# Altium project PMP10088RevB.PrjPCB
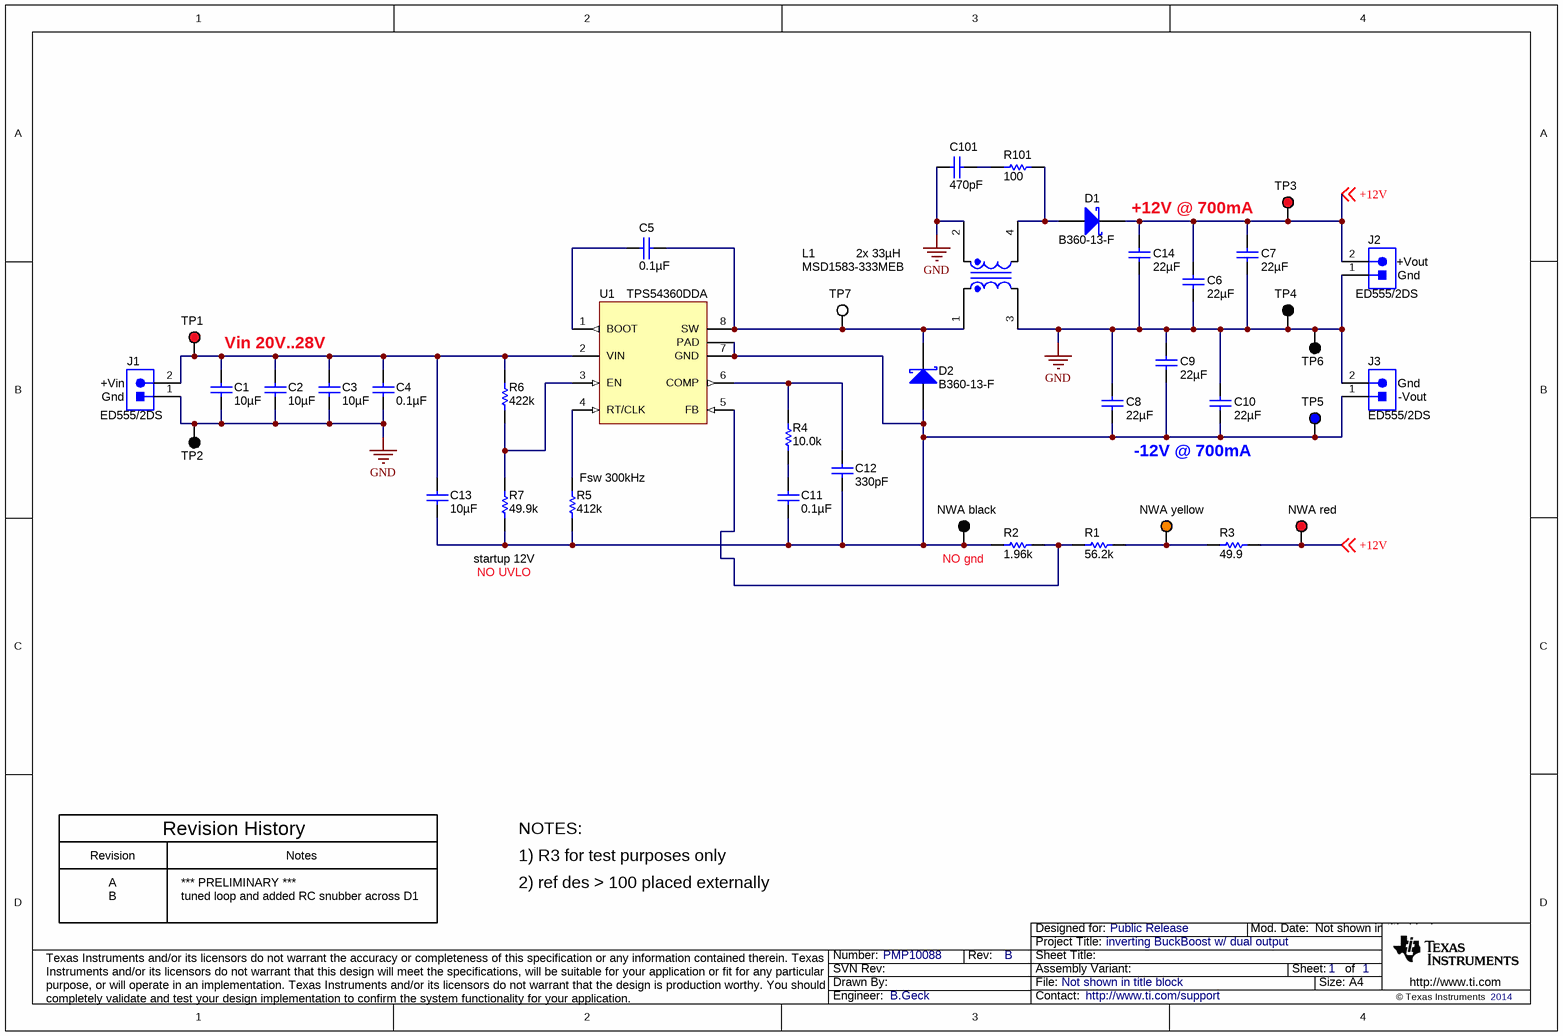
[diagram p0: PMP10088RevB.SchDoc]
TechSupport: http://www.ti.com/support; SCH_Rev: B; PRJ_Title: inverting BuckBoost w/ dual output; PRJ_Number: PMP10088; PRJ_Engineer: B.Geck; PRJ_Customer: Public Release; PCB_Rev: A; PCB_Layout: B.Geck; CopyrightYear: 2014
1 sheet, 40 parts. Net scope: global (net labels, ports and power ports of the same name join across sheets).
Board file: PMP10088RevA.PcbDoc

## Sheet PMP10088RevB.SchDoc
size A4; Date: Not shown in title block; ApprovedBy: Not shown in title block; CheckedBy: Not shown in title block; Author: Not shown in title block; CompanyName: Not shown in title block; Engineer: Not shown in title block; Organization: Not shown in title block; Address1: Not shown in title block; Address2: Not shown in title block; Address3: Not shown in title block; Address4: Not shown in title block; DocumentNumber: 1; Revision: Use project parameter SCH_Rev; SheetNumber: 1; SheetTotal: 1; PageSetup: Record=PageOptions¦CenterHorizontal=True¦CenterVertical=True¦PrintScale=0.70¦XCorrection=1.00¦YCorrection=1.00¦PrintKind=0¦BorderSize=5000000¦LeftOffset=0¦BottomOffset=0¦Orientation=2¦PaperLength=1000¦PaperWidth=1000¦Scale=100¦PaperSource=15¦PrintQuality=600¦MediaType=1¦DitherType=10¦PaperKind=A4¦PrintScaleMode=1

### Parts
C1  ValueDisplayed: 10µF  [1210]  (hidden comment: GRM32ER71H106KA12L)
C2  ValueDisplayed: 10µF  [1210]  (hidden comment: GRM32ER71H106KA12L)
C3  ValueDisplayed: 10µF  [1210]  (hidden comment: GRM32ER71H106KA12L)
C4  ValueDisplayed: 0.1µF  [0603]  (hidden comment: GRM188R71H104KA93D)
C5  ValueDisplayed: 0.1µF  [0603]  (hidden comment: GRM188R71H104KA93D)
C6  ValueDisplayed: 22µF  [1210]  (hidden comment: GRM32ER71E226KE15L)
C7  ValueDisplayed: 22µF  [1210]  (hidden comment: GRM32ER71E226KE15L)
C8  ValueDisplayed: 22µF  [1210]  (hidden comment: GRM32ER71E226KE15L)
C9  ValueDisplayed: 22µF  [1210]  (hidden comment: GRM32ER71E226KE15L)
C10  ValueDisplayed: 22µF  [1210]  (hidden comment: GRM32ER71E226KE15L)
C11  ValueDisplayed: 0.1µF  [0603]  (hidden comment: GRM188R71H104KA93D)
C12  ValueDisplayed: 330pF  [0603]  (hidden comment: GRM188R71H331KA01D)
C13  ValueDisplayed: 10µF  [1210]  (hidden comment: GRM32ER71H106KA12L)
C14  ValueDisplayed: 22µF  [1210]  (hidden comment: GRM32ER71E226KE15L)
C101  ValueDisplayed: 470pF  [0603]  (hidden comment: GRM188R72A471KA01D)
D1  B360-13-F  [SMC]
D2  B360-13-F  [SMC]
J1  ED555/2DS  [TERM_BLK_ED555-2DS]
J2  ED555/2DS  [TERM_BLK_ED555-2DS]
J3  ED555/2DS  [TERM_BLK_ED555-2DS]
L1  MSD1583-333MEB  ValueDisplayed: 2x 33µH  [IND_MSD1583]
NWA_black  5001  [Keystone5001]  (value not drawn)
NWA_red  5000  [Keystone5000]  (value not drawn)
NWA_yellow  5003  [Keystone5003]  (value not drawn)
R1  value 56.2k  [0603]  (hidden comment: CRCW060356K2FKEA)
R2  value 1.96k  [0603]  (hidden comment: CRCW06031K96FKEA)
R3  value 49.9  [0603]  (hidden comment: CRCW060349R9FKEA)
R4  ValueDisplayed: 10.0k  [0603]  (hidden comment: CRCW060310K0FKEA)
R5  value 412k  [0603]  (hidden comment: CRCW0603412KFKEA)
R6  value 422k  [0603]  (hidden comment: CRCW0603422KFKEA)
R7  value 49.9k  [0603]  (hidden comment: CRCW060349K9FKEA)
R101  ValueDisplayed: 100  [1206]  (hidden comment: CRCW1206100RJNEA)
TP1  5000  [Keystone5000]  (value not drawn)
TP2  5001  [Keystone5001]  (value not drawn)
TP3  5000  [Keystone5000]  (value not drawn)
TP4  5001  [Keystone5001]  (value not drawn)
TP5  5117  [Keystone5117]  (value not drawn)
TP6  5001  [Keystone5001]  (value not drawn)
TP7  5002  [Keystone5002]  (value not drawn)
U1  TPS54360DDA  [DDA0008E_N]

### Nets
GND: C1.2 C2.2 C3.2 C4.2 C6.2 C7.2 C8.1 C9.1 C10.1 C14.2 C101.2 J1.1 J2.1 J3.2 L1.2 L1.3 TP2.1 TP4.1 TP6.1
+12V: C6.1 C7.1 C14.1 D1.1(K) J2.2 NWA_red.1 R3.1 TP3.1 ; off-sheet +12V
NetC1_1: C1.1 C2.1 C3.1 C4.1 C13.1 J1.2 R6.2 TP1.1 U1.2(VIN)
NetC5_1: C5.1 U1.1(BOOT)
NetC5_2: C5.2 D2.1(K) L1.1 TP7.1 U1.8(SW)
NetC8_2: C8.2 C9.2 C10.2 C11.2 C12.2 C13.2 D2.2(A) J3.1 NWA_black.1 R2.1 R5.1 R7.1 TP5.1 U1.7(GND) U1.9(PAD)
NetC11_1: C11.1 R4.1
NetC12_1: C12.1 R4.2 U1.6(COMP)
NetC101_1: C101.1 R101.1
NetD1_2: D1.2(A) L1.4 R101.2
NetNWA_yellow_1: NWA_yellow.1 R1.2 R3.2
NetR1_1: R1.1 R2.2 U1.5(FB)
NetR5_2: R5.2 U1.4(RT/CLK)
NetR6_1: R6.1 R7.2 U1.3(EN)

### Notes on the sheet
- +12V @ 700mA
- (near J2) Gnd
- (near J2) +Vout
- (near J1) +Vin
- Vin 20V..28V
- (near J3) Gnd
- (near J1) Gnd
- -12V @ 700mA
- (near J3) -Vout
- (near R5) Fsw 300kHz
- startup 12V
- NO UVLO
- NO gnd
- Revision
- Revision History
- Notes
- NOTES:
- 1) R3 for test purposes only
- A
- B
- *** PRELIMINARY ***
- tuned loop and added RC snubber across D1
- 2) ref des > 100 placed externally

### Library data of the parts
C1-C3 C13 = GRM32ER71H106KA12L: CAP, CERM, 10uF, 50V, +/-10%, X7R, 1210; Manufacturer: MuRata; Polarized: N; CompType: Capacitor; U/M: EA; Cap_F: 0.00001; Tolerance_%: 10; Value1: Unknown; VDC_V: 50; TaMin_C: -55; TaMax_C: 125
C4 C5 C11 = GRM188R71H104KA93D: CAP, CERM, 0.1uF, 50V, +/-10%, X7R, 0603; Manufacturer: MuRata; Polarized: N; CompType: Capacitor; U/M: EA; Cap_F: 0.0000001; Tolerance_%: 10; Value1: Unknown; VDC_V: 50; TaMin_C: -55; TaMax_C: 125
C6-C10 C14 = GRM32ER71E226KE15L: CAP, CERM, 22uF, 25V, +/-10%, X7R, 1210; Manufacturer: MuRata; Polarized: N; CompType: Capacitor; U/M: EA; Cap_F: 0.000022; Tolerance_%: 10; Value1: Unknown; VDC_V: 25; TaMin_C: -55; TaMax_C: 125
C12 = GRM188R71H331KA01D: CAP, CERM, 330 pF, 50 V, +/- 10%, X7R, 0603; Manufacturer: MuRata; Polarized: N; CompType: Capacitor; Value: 330pF; U/M: EA; Cap_F: 0.00000000033; Tolerance_%: 10; Value1: Unknown; VDC_V: 50; Value2: 50V; TaMin_C: -55; TaMax_C: 125
C101 = GRM188R72A471KA01D: CAP, CERM, 470 pF, 100 V, +/- 10%, X7R, 0603; Manufacturer: MuRata; Polarized: N; CompType: Capacitor; Value: 470pF; U/M: EA; Cap_F: 0.00000000047; Tolerance_%: 10; Value1: Unknown; VDC_V: 100; Value2: 100V; TaMin_C: -55; TaMax_C: 125
D1 D2 = B360-13-F: Diode, Schottky, 60V, 3A, SMC; Manufacturer: Diodes Inc.; U/M: EA; Vf_V: 0.7; Value2: 0.7V; Io_A: 3; Vr_V: 60; TJmax_C: 125; RJC_CperW: 20
J1-J3 = ED555/2DS: Terminal Block, 6A, 3.5mm Pitch, 2-Pos, TH; Manufacturer: On-Shore Technology; SymbolCreator: a0412235; CompType: Connector; U/M: EA
L1 = MSD1583-473MEB: Coupled inductor, 33uH, 2.16A, 0.083 ohm, +/-20%, SMD; Manufacturer: Coilcraft; SymbolCreator: a0412235; Ind_H: 22.0E-6; DCR_ohm: 0.033; Isat: 9.80; Tolerance_%: 20
NWA_black TP2 TP4 TP6 = 5001: Test Point, Miniature, Black, TH; Manufacturer: Keystone; CompType: Test Point Loop; U/M: EA
NWA_red TP1 TP3 = 5000: Test Point, Miniature, Red, TH; Manufacturer: Keystone; CompType: Test Point Loop; U/M: EA
NWA_yellow = 5003: Test Point, Miniature, Orange, TH; Manufacturer: Keystone; CompType: Test Point Loop; U/M: EA
R1 = CRCW060356K2FKEA: RES, 56.2k ohm, 1%, 0.1W, 0603; Manufacturer: Vishay-Dale; CompType: Resistor; Res_ohm: 56200; Value_Code: 56k2; Tolerance_%: 1; Power_W: 0.1; VDC_V: 75; TempCo: 100 ppm/C; EIA_Code: E96; U/M: EA
R2 = CRCW06031K96FKEA: RES, 1.96k ohm, 1%, 0.1W, 0603; Manufacturer: Vishay-Dale; CompType: Resistor; Res_ohm: 1960; Value_Code: 1k96; Tolerance_%: 1; Power_W: 0.1; VDC_V: 75; TempCo: 100 ppm/C; EIA_Code: E96; U/M: EA
R3 = CRCW060349R9FKEA: RES, 49.9 ohm, 1%, 0.1W, 0603; Manufacturer: Vishay-Dale; CompType: Resistor; Value_Code: 49R9; Tolerance_%: 1; Power_W: 0.1; VDC_V: 75; TempCo: 100 ppm/C; EIA_Code: E96; U/M: EA
R4 = CRCW060310K0FKEA: RES, 10.0 k, 1%, 0.1 W, 0603; Manufacturer: Vishay-Dale; CompType: Resistor; Value: 10.0k; Res_ohm: 10000; Value_Code: 10k0; Tolerance_%: 1; Power_W: 0.1; Value2: 0.1W; VDC_V: 75; TempCo: 100 ppm/C; EIA_Code: E96; U/M: EA
R5 = CRCW0603412KFKEA: RES, 412k ohm, 1%, 0.1W, 0603; Manufacturer: Vishay-Dale; CompType: Resistor; Res_ohm: 412000; Tolerance_%: 1; Power_W: 0.1; VDC_V: 75; TempCo: 100 ppm/C; EIA_Code: E96; U/M: EA
R6 = CRCW0603422KFKEA: RES, 422k ohm, 1%, 0.1W, 0603; Manufacturer: Vishay-Dale; CompType: Resistor; Res_ohm: 422000; Tolerance_%: 1; Power_W: 0.1; VDC_V: 75; TempCo: 100 ppm/C; EIA_Code: E96; U/M: EA
R7 = CRCW060349K9FKEA: RES, 49.9k ohm, 1%, 0.1W, 0603; Manufacturer: Vishay-Dale; CompType: Resistor; Res_ohm: 49900; Value_Code: 49k9; Tolerance_%: 1; Power_W: 0.1; VDC_V: 75; TempCo: 100 ppm/C; EIA_Code: E96; U/M: EA
R101 = CRCW1206100RJNEA: RES, 100, 5%, 0.25 W, 1206; Manufacturer: Vishay-Dale; CompType: Resistor; Value: 100; Value_Code: 100R; Tolerance_%: 5; Power_W: 0.25; Value2: 0.25W; VDC_V: 200; TempCo: 200 ppm/C; EIA_Code: E24; U/M: EA
TP5 = 5117: Test Point, Miniature, Blue, TH; Manufacturer: Keystone; CompType: Test Point Loop; U/M: EA
TP7 = 5002: Test Point, Miniature, White, TH; Manufacturer: Keystone; CompType: Test Point Loop; U/M: EA
U1 = TPS54360DDA: 60 V Input, 3.5 A, Step Down DC-DC Converter with Eco-mode, DDA0008E; Alternate Manufacturer: None; Manufacturer: Texas Instruments; SymbolCreator: a0411947; CompType: IC; U/M: EA

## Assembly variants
001: all parts fitted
